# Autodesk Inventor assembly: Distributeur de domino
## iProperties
Shininess: 41.0
Length Units: 11269
Angle Units: 11279
Time Units: 11290
Mass Units: 11283
Length Display Precision: 3
Angle Display Precision: 2
Created: 2002-05
Part Number: Distributeur de domino
Document SubType Name: Assemblage
Designer: Flavien MARTY
Density: 0.0
Volumn: 0.0
Area: 0.0
PropertySet Name: Model Information
Control State: 0
Master: False
Checked Out: False
Author: Flavien MARTY
